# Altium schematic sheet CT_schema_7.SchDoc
size 368 x 245 mm
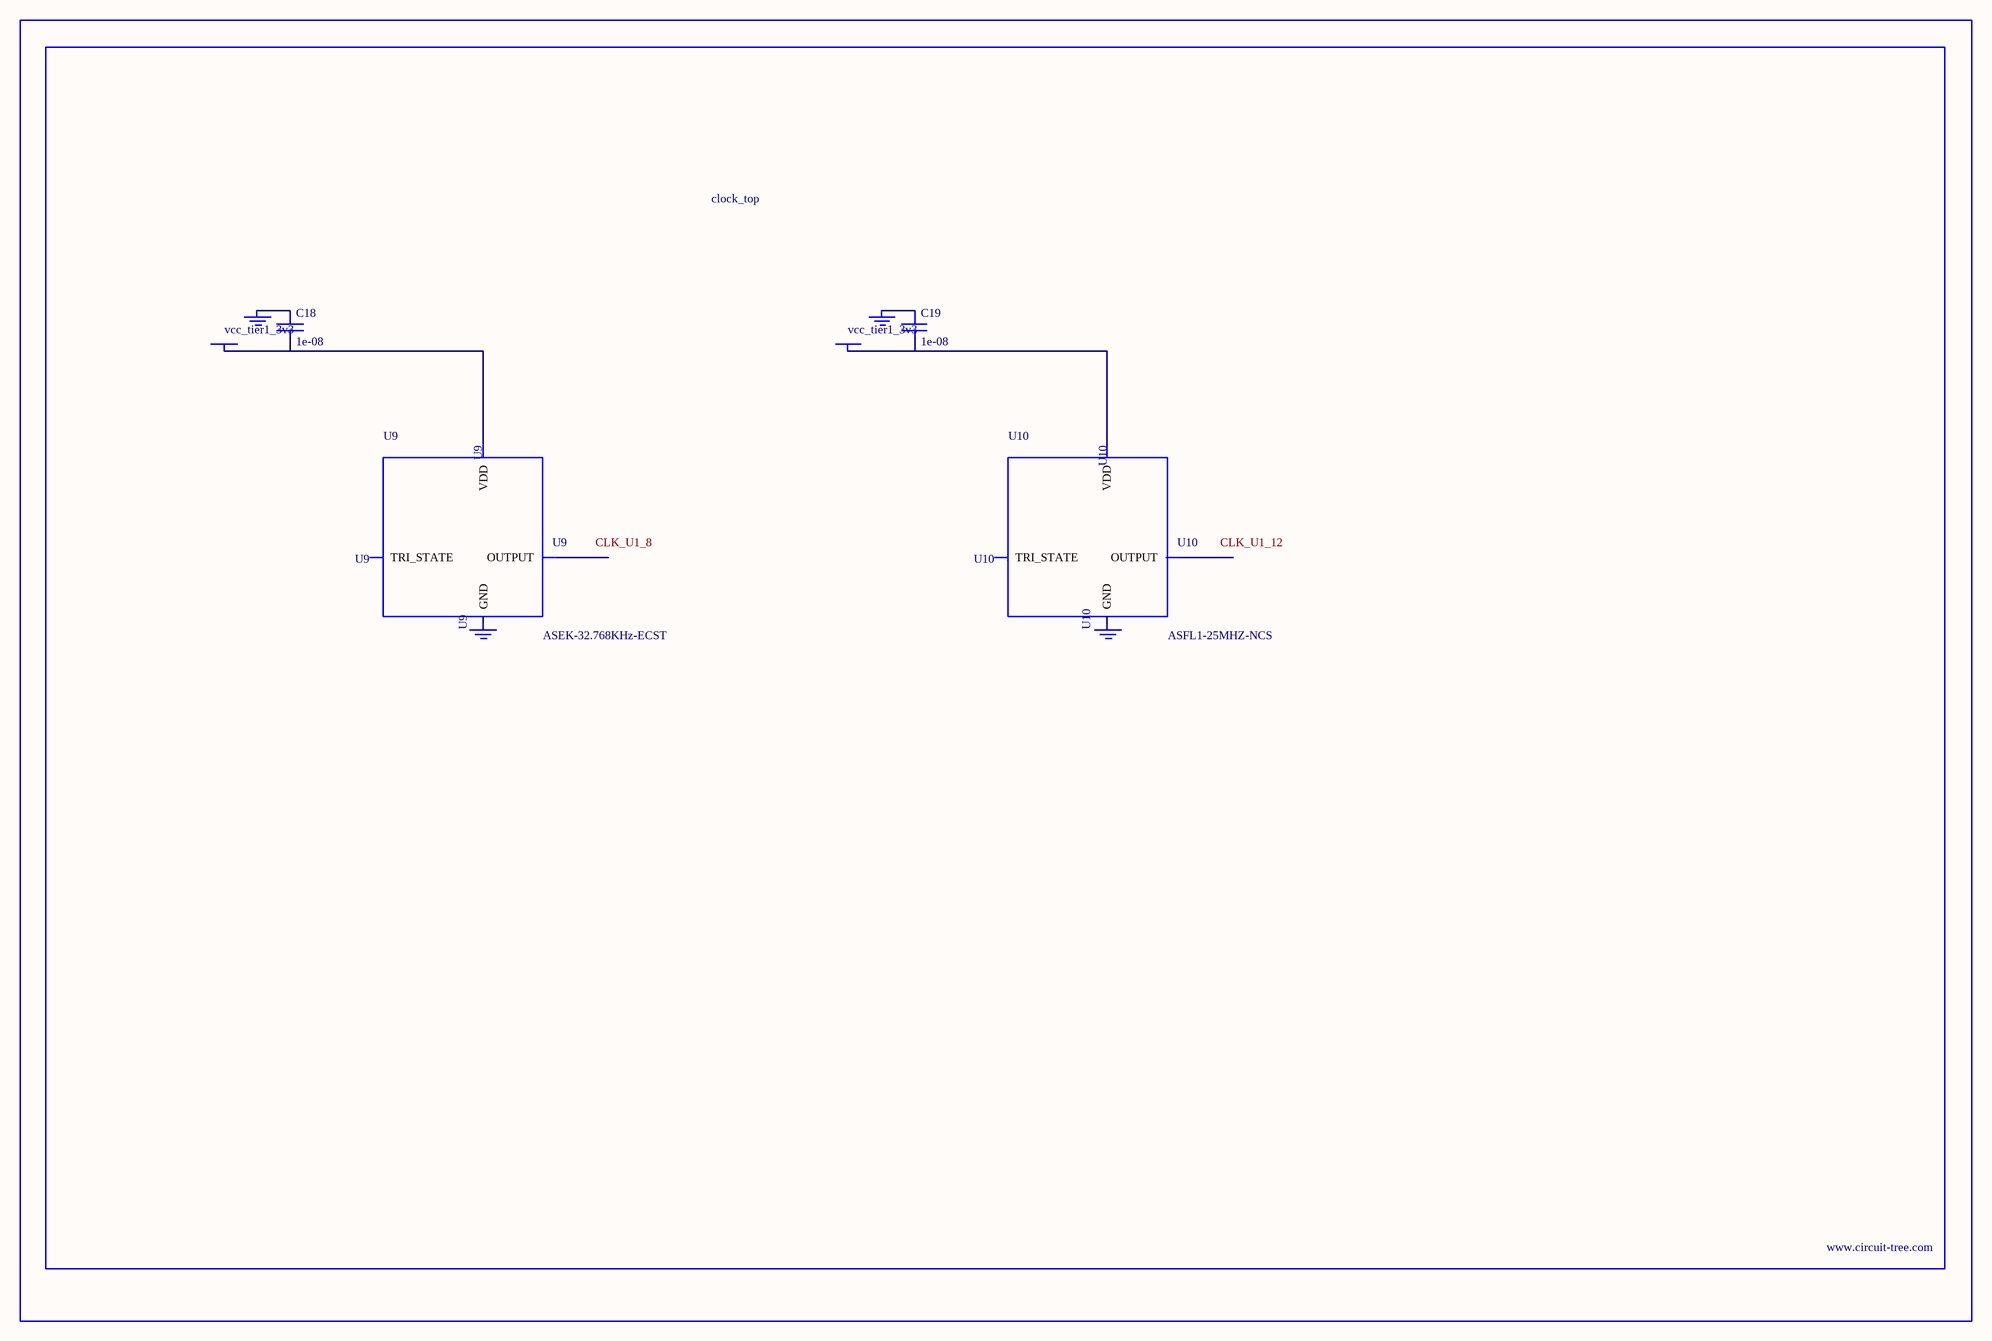
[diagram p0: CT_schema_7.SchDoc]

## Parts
BORDER6  (no value)
C18  1e-08  [C0402]
C19  1e-08  [C0402]
GND_INSTANCE_6_0  (no value)
GND_INSTANCE_6_1  (no value)
GND_INSTANCE_6_2  (no value)
GND_INSTANCE_6_3  (no value)
POWER_INSTANCE_6_0  vcc_tier1_3v3
POWER_INSTANCE_6_1  vcc_tier1_3v3
U9  ASEK-32.768KHz-ECST  [ASEK]
U10  ASFL1-25MHZ-NCS  [ASFL1]

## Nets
NetC18_1: C18.1 GND_INSTANCE_6_0.0(GND)
NetC18_2: C18.2 POWER_INSTANCE_6_0.0(PWR) U9.4(VDD)
NetC19_1: C19.1 GND_INSTANCE_6_2.0(GND)
NetC19_2: C19.2 POWER_INSTANCE_6_1.0(PWR) U10.4(VDD)

Not connected (* = marked no-connect by the designer): GND_INSTANCE_6_1 0(GND); GND_INSTANCE_6_3 0(GND); U9 1(TRI_STATE) 2(GND) 3(OUTPUT); U10 1(TRI_STATE) 2(GND) 3(OUTPUT)

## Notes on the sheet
- Labels drawn without touching a wire or pin: CLK_U1_8, CLK_U1_12

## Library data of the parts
BORDER6 = BORDER_PAGE6
C18 C19 = C0402C103K3RAC
GND_INSTANCE_6_0-GND_INSTANCE_6_3 = GND
POWER_INSTANCE_6_0 POWER_INSTANCE_6_1 = PWR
